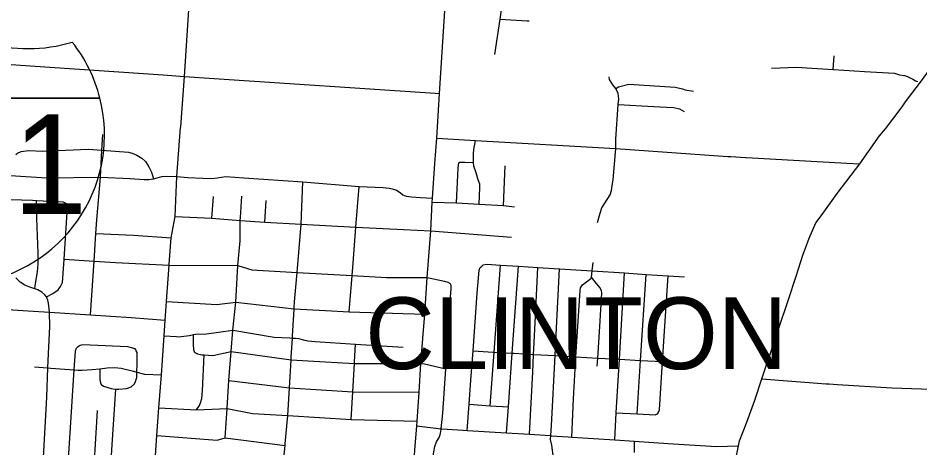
# Model space of a CAD drawing. Extents: x 1755200 to 1902939, y 644115 to 788070.
# Drawn here: x 1829686 to 1840977, y 741550 to 746938 of the extents above; entities that cross this region are included whole.
import ezdxf

# ---------------------------------------------------------------- set-up
doc = ezdxf.new("R2010")
doc.units = 0
for name, color, linetype in [('GM_X_City_Street', 7, 'Continuous'), ('GM_X_County_Road', 7, 'Continuous'), ('GM_X_Interstate_Shield', 7, 'Continuous'), ('GM_X_Township_Road', 7, 'Continuous'), ('GM_X_Township_Text', 7, 'Continuous')]:
    doc.layers.add(name, color=color, linetype=linetype)

msp = doc.modelspace()

# ---------------------------------------------------------------- linework, layer by layer
at = {"layer": 'GM_X_City_Street'}
for points in [[(1834905, 745116), (1834927, 745433), (1834962, 745993), (1835045, 747292), (1835103, 748151), (1835122, 748425), (1835145, 748748)], [(1840798, 745888), (1840995, 746153), (1841299, 746563), (1841340, 746619), (1841440, 746774), (1841449, 746831), (1841461, 746912), (1841483, 747247), (1841494, 747414)], [(1835655, 746481), (1835722, 746924), (1835769, 747251)], [(1831723, 745574), (1831771, 746206), (1831823, 747039)], [(1835722, 746924), (1836060, 746904), (1836087, 746903)], [(1839891, 746294), (1839905, 746466)], [(1839118, 746312), (1839433, 746321), (1839891, 746294), (1839894, 746294), (1840281, 746270), (1840660, 746248), (1840722, 746226), (1840783, 746219), (1840821, 746204), (1840863, 746185), (1840890, 746170), (1840920, 746152), (1840948, 746141)], [(1831504, 746225), (1831771, 746206), (1832143, 746181)], [(1836942, 744374), (1836975, 744492), (1836996, 744559), (1837031, 744619), (1837098, 744723), (1837117, 744776), (1837123, 744838), (1837135, 744910), (1837168, 745302), (1837172, 745420), (1837201, 745856), (1837206, 745924), (1837199, 745994), (1837169, 746057), (1837133, 746101), (1837092, 746166), (1837085, 746203)], [(1837169, 746057), (1837202, 746076), (1837333, 746108), (1837913, 746073), (1838006, 746053), (1838038, 746040), (1838143, 746020)], [(1834909, 745996), (1834962, 745993)], [(1837201, 745856), (1837646, 745831), (1837803, 745821), (1837896, 745815), (1837965, 745801), (1838025, 745765)], [(1831354, 740680), (1831376, 740992), (1831399, 741329), (1831424, 741705), (1831450, 742054), (1831481, 742467), (1831516, 742955), (1831530, 743153), (1831546, 743384), (1831579, 743843), (1831579, 743852), (1831603, 744183), (1831655, 744452), (1831676, 744954), (1831722, 745565), (1831723, 745574)], [(1830595, 743220), (1830640, 743893), (1830662, 744239), (1830674, 744410), (1830717, 744946), (1830736, 745281), (1830747, 745480)], [(1834927, 745433), (1835415, 745403), (1837168, 745302), (1838572, 745205), (1838599, 745204)], [(1835458, 744607), (1835469, 744816), (1835466, 744857), (1835448, 744911), (1835420, 744999), (1835394, 745082), (1835388, 745127), (1835388, 745236), (1835394, 745291), (1835415, 745403)], [(1829657, 745229), (1829681, 745243), (1829725, 745265), (1829816, 745278), (1829998, 745268), (1830565, 745293), (1830736, 745281), (1831068, 745258), (1831114, 745245), (1831174, 745220), (1831236, 745180), (1831283, 745139), (1831325, 745074), (1831356, 745007), (1831383, 744924)], [(1834585, 740456), (1834629, 741157), (1834654, 741523), (1834677, 741826), (1834681, 741888), (1834707, 742251), (1834730, 742608), (1834755, 742924), (1834779, 743226), (1834810, 743687), (1834852, 744272), (1834872, 744632), (1834875, 744681), (1834905, 745116)], [(1835175, 744623), (1835193, 744969), (1835198, 745060), (1835203, 745123), (1835217, 745132), (1835281, 745132), (1835388, 745127)], [(1835762, 744587), (1835785, 745086)], [(1829588, 744965), (1830047, 744935), (1830717, 744946), (1831090, 744928), (1831267, 744914), (1831324, 744913), (1831383, 744924), (1831428, 744937), (1831487, 744953), (1831548, 744958), (1831676, 744954), (1831810, 744941), (1831998, 744931), (1832109, 744927), (1832177, 744934), (1832232, 744944), (1832286, 744951), (1832512, 744936), (1833252, 744884), (1833957, 744829), (1834257, 744813), (1834332, 744805), (1834388, 744794), (1834425, 744779), (1834468, 744751), (1834502, 744724), (1834546, 744706), (1834613, 744697), (1834723, 744691), (1834875, 744681)], [(1833145, 743316), (1833148, 743381), (1833179, 743750), (1833229, 744356), (1833252, 744884)], [(1833832, 743257), (1833869, 743710), (1833882, 743867), (1833917, 744318), (1833957, 744829)], [(1829593, 744665), (1829866, 744656), (1829918, 744653), (1830250, 744634), (1830278, 744622), (1830292, 744610)], [(1832112, 744429), (1832133, 744702)], [(1832471, 744439), (1832487, 744704)], [(1829895, 743544), (1829904, 743613), (1829928, 743759), (1829938, 743856), (1829938, 743990), (1829922, 744425), (1829918, 744653)], [(1830043, 743444), (1830123, 743485), (1830188, 743532), (1830218, 743574), (1830243, 743622), (1830252, 743738), (1830263, 743917), (1830304, 744566), (1830302, 744590), (1830292, 744610)], [(1832775, 744381), (1832793, 744651)], [(1834872, 744632), (1835175, 744623), (1835458, 744607), (1835762, 744587), (1835902, 744572)], [(1831655, 744452), (1832112, 744429), (1832468, 744401), (1832775, 744381), (1833229, 744356), (1833917, 744318), (1834510, 744286), (1834852, 744272)], [(1832412, 743378), (1832438, 743837), (1832465, 744146), (1832468, 744401), (1832471, 744439)], [(1830662, 744239), (1831133, 744217), (1831603, 744183)], [(1834852, 744272), (1834852, 744272), (1835863, 744194)], [(1830263, 743917), (1830640, 743893), (1830908, 743876), (1831579, 743843), (1832438, 743837), (1832611, 743784), (1833179, 743750), (1833869, 743710), (1834299, 743685), (1834810, 743687), (1835027, 743640), (1835067, 743629), (1835095, 743611)], [(1836617, 741686), (1836639, 742166), (1836671, 742693), (1836722, 743525), (1836728, 743555), (1836752, 743593), (1836819, 743643), (1836855, 743673), (1836866, 743690), (1836874, 743768), (1836885, 743875)], [(1835310, 741771), (1835334, 742097), (1835355, 742399), (1835382, 742766), (1835436, 743489), (1835460, 743780), (1835471, 743811), (1835494, 743830)], [(1835494, 743830), (1835510, 743844), (1835556, 743852), (1835727, 743841), (1835953, 743827), (1836195, 743811), (1836466, 743794), (1836874, 743768), (1837277, 743743), (1837548, 743725), (1837824, 743708), (1838029, 743695)], [(1835595, 742079), (1835646, 742751), (1835727, 743841)], [(1835801, 741740), (1835825, 742064), (1835874, 742738), (1835953, 743827)], [(1836088, 741722), (1836131, 742499), (1836140, 742723), (1836143, 742791), (1836163, 743202), (1836195, 743811)], [(1836388, 741426), (1836368, 741585), (1836354, 741655), (1836357, 741705), (1836365, 741831), (1836410, 742708), (1836419, 742887), (1836466, 743794)], [(1829954, 740764), (1829942, 740783), (1829942, 740813), (1829963, 740887), (1829975, 740929), (1829984, 740969), (1829994, 741193), (1830006, 741430), (1830045, 742187), (1830061, 742555), (1830068, 742728), (1830083, 743074), (1830078, 743254), (1830066, 743365), (1830058, 743401), (1830043, 743444), (1830021, 743470), (1829985, 743504), (1829935, 743531), (1829895, 743544), (1829834, 743564), (1829770, 743591), (1829712, 743629), (1829660, 743682)], [(1836938, 742577), (1836944, 742677), (1836968, 743074), (1836995, 743493), (1836991, 743521), (1836973, 743557), (1836923, 743617), (1836866, 743690)], [(1837156, 741652), (1837176, 741989), (1837215, 742662), (1837277, 743743)], [(1837435, 741976), (1837478, 742647), (1837548, 743725)], [(1837693, 741977), (1837701, 741989), (1837715, 742029), (1837754, 742632), (1837824, 743708)], [(1839395, 743603), (1839427, 743703)], [(1834846, 740436), (1834828, 740551), (1834851, 740851), (1834867, 741120), (1834870, 741182), (1834887, 741478), (1834902, 741570), (1834925, 741628), (1834959, 741680), (1834971, 741716), (1834980, 741756), (1834983, 741791), (1835004, 741988), (1835040, 742543), (1835081, 743172), (1835107, 743549), (1835107, 743585), (1835095, 743611)], [(1831546, 743384), (1832175, 743349), (1832412, 743378), (1833143, 743295), (1833536, 743273), (1833832, 743257), (1834779, 743226)], [(1832304, 742049), (1832327, 742394), (1832353, 742758), (1832376, 743027), (1832412, 743378)], [(1833123, 742950), (1833143, 743289), (1833143, 743295), (1833145, 743316)], [(1829483, 743291), (1830078, 743254), (1830595, 743220), (1831104, 743187), (1831530, 743153)], [(1831516, 742955), (1831670, 742949), (1831706, 742942), (1831728, 742946), (1831833, 742961), (1831884, 742972), (1831907, 742976), (1831947, 742982), (1832017, 742977), (1832376, 743027), (1832892, 742939), (1833087, 742930)], [(1831907, 742742), (1831901, 742742), (1831887, 742778), (1831882, 742850), (1831884, 742972)], [(1833087, 742930), (1833090, 742929), (1833122, 742928), (1833158, 742926), (1833198, 742920), (1833260, 742907), (1833314, 742893), (1833406, 742886), (1833912, 742852), (1834509, 742813)], [(1833107, 742688), (1833122, 742928), (1833122, 742930), (1833123, 742950)], [(1833900, 742630), (1833900, 742630), (1833912, 742852)], [(1830316, 741413), (1830337, 741740), (1830387, 742529), (1830406, 742768), (1830419, 742800), (1830439, 742822)], [(1830439, 742822), (1830463, 742839), (1830496, 742847), (1831057, 742823), (1831117, 742803), (1831143, 742795), (1831161, 742776)], [(1831175, 742501), (1831179, 742602), (1831179, 742710), (1831176, 742748), (1831166, 742768), (1831161, 742776)], [(1831907, 742742), (1831931, 742730), (1831987, 742719), (1832015, 742717), (1832123, 742708), (1832353, 742758), (1833105, 742654), (1833318, 742642), (1833898, 742609), (1834730, 742608), (1834731, 742608)], [(1835382, 742766), (1835634, 742752), (1835646, 742751)], [(1835646, 742751), (1835874, 742738), (1835887, 742737), (1835896, 742737)], [(1831920, 742026), (1831957, 742082), (1831975, 742128), (1831988, 742170), (1831994, 742266), (1832015, 742717)], [(1833032, 741603), (1833065, 741956), (1833085, 742305), (1833105, 742654), (1833107, 742674), (1833107, 742688)], [(1833858, 741906), (1833878, 742253), (1833898, 742609), (1833900, 742630)], [(1835896, 742737), (1836140, 742723), (1836410, 742708), (1836671, 742693), (1836944, 742677), (1837215, 742662), (1837478, 742647), (1837754, 742632), (1837954, 742620)], [(1829891, 742569), (1830057, 742556)], [(1830057, 742556), (1830061, 742555), (1830097, 742552), (1830387, 742529), (1830437, 742526)], [(1830437, 742526), (1830489, 742524), (1830615, 742533), (1830709, 742543), (1830802, 742555), (1830892, 742558), (1830976, 742550), (1831133, 742514), (1831175, 742501), (1831268, 742475), (1831481, 742467)], [(1830709, 742543), (1830708, 742471), (1830709, 742409), (1830718, 742367), (1830727, 742345), (1830755, 742324), (1830850, 742296), (1830896, 742287), (1830909, 742287), (1830950, 742288), (1831044, 742294), (1831103, 742317), (1831142, 742352), (1831158, 742384), (1831173, 742433), (1831175, 742501)], [(1834731, 742608), (1834776, 742604), (1835040, 742543)], [(1830816, 740686), (1830854, 741383), (1830862, 741527), (1830909, 742287)], [(1832327, 742394), (1833085, 742305), (1833878, 742253), (1834707, 742251)], [(1839840, 742353), (1839891, 742350), (1839946, 742347)], [(1835334, 742097), (1835595, 742079), (1835825, 742064)], [(1830588, 740696), (1830642, 741395), (1830652, 741525), (1830682, 742018)], [(1831450, 742054), (1831920, 742026), (1832304, 742043), (1832623, 741983), (1833065, 741956), (1833858, 741906), (1834681, 741888)], [(1832281, 741676), (1832304, 742043), (1832304, 742049)], [(1837176, 741989), (1837435, 741976), (1837663, 741965), (1837693, 741977)], [(1834677, 741826), (1834983, 741791), (1834992, 741791)], [(1834992, 741791), (1835259, 741774), (1835310, 741771), (1835801, 741740), (1836088, 741722), (1836351, 741705), (1836357, 741705), (1836361, 741704), (1836362, 741704)], [(1831424, 741705), (1832181, 741647), (1832281, 741676), (1833030, 741582)], [(1836362, 741704), (1836573, 741688)], [(1837402, 741492), (1837405, 741636)], [(1832960, 740643), (1832964, 740749), (1832976, 740923), (1832996, 741221), (1833003, 741300), (1833030, 741582), (1833031, 741594), (1833032, 741603)]]:
    msp.add_lwpolyline(points, dxfattribs=at)
at = {"layer": 'GM_X_County_Road'}
for points in [[(1829318, 746346), (1829355, 746362), (1829376, 746366), (1829394, 746368), (1829415, 746367), (1829837, 746340), (1831504, 746225)], [(1832143, 746181), (1834909, 745996)], [(1839543, 744054), (1839589, 744181), (1839673, 744373), (1839752, 744478), (1839940, 744741), (1840225, 745111), (1840471, 745460), (1840547, 745550), (1840753, 745827), (1840798, 745888)], [(1838599, 745204), (1838608, 745203), (1838795, 745192), (1838801, 745192), (1840060, 745121), (1840225, 745111)], [(1839427, 743703), (1839515, 743979), (1839543, 744054)], [(1838565, 740349), (1838572, 740451), (1838594, 740714), (1838594, 740753), (1838624, 741101), (1838640, 741220), (1838668, 741395), (1838705, 741577), (1838719, 741639), (1838808, 741872), (1838908, 742149), (1838998, 742415), (1839366, 743513), (1839395, 743603)], [(1838998, 742415), (1839802, 742355), (1839840, 742353)], [(1839946, 742347), (1840626, 742305), (1840995, 742291), (1841158, 742282)]]:
    msp.add_lwpolyline(points, dxfattribs=at)
at = {"layer": 'GM_X_Interstate_Shield'}
for p, q in [((1827827, 745934), (1830712, 745934)), ((1830712, 745934), (1827827, 745934)), ((1830712, 745934), (1827827, 745934))]:
    msp.add_line(p, q, dxfattribs=at)
for centre, start, end in [((1829817, 748430), 253.0091, 286.9909), ((1828894, 745474), 14.1934, 38.331), ((1828894, 745474), 281.537, 14.1934)]:
    msp.add_arc(centre, 1875, start, end, dxfattribs=at)
at = {"layer": 'GM_X_Township_Road'}
msp.add_lwpolyline([(1836573, 741688), (1836617, 741686), (1836757, 741678), (1837156, 741652), (1837405, 741636), (1837827, 741608), (1838430, 741569), (1838705, 741577)], dxfattribs=at)

# ---------------------------------------------------------------- texts
at = {"layer": 'GM_X_Interstate_Shield'}
msp.add_text('71', height=1250, dxfattribs=at).set_placement((1828692, 744481))
at = {"layer": 'GM_X_Township_Text'}
msp.add_text('CLINTON', height=900, rotation=0, dxfattribs=at).set_placement((1834033, 742538))

doc.saveas('drawing.dxf')
